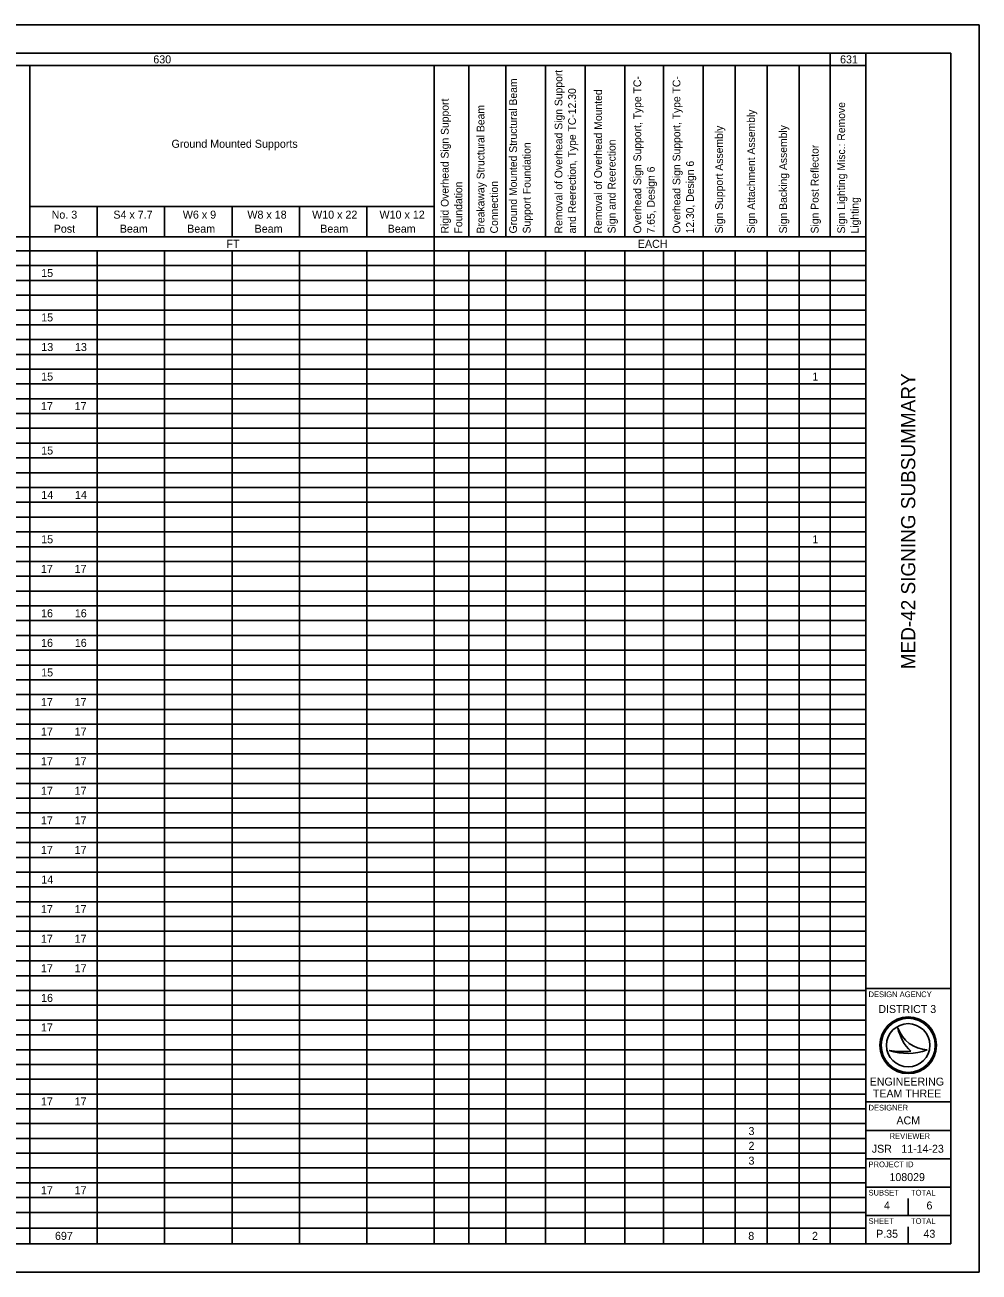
# Model space of a CAD drawing. Extents: x 0 to 34, y 0 to 22.
# Drawn here: x 17.17 to 34, y 0 to 22 of the extents above; entities that cross this region are included whole.
import ezdxf

# ---------------------------------------------------------------- set-up
doc = ezdxf.new("R2010")
doc.units = 0
for name, color, linetype in [('SH_Border', 7, 'Continuous'), ('SH_Cut_Line', 7, 'Continuous'), ('SH_Data', 7, 'Continuous'), ('SH_Text', 7, 'Continuous')]:
    doc.layers.add(name, color=color, linetype=linetype)

msp = doc.modelspace()

# ---------------------------------------------------------------- linework, layer by layer
at = {"layer": 'SH_Border'}
for p, q in [((32, 0.5), (32, 21.5)), ((32, 5), (33.5, 5)), ((32, 3), (33.5, 3)), ((32, 2.5), (33.5, 2.5)), ((32, 2), (33.5, 2)), ((32, 1.5), (33.5, 1.5)), ((32, 1), (33.5, 1))]:
    msp.add_line(p, q, dxfattribs=at)
msp.add_lwpolyline([(1.5, 21.5), (33.5, 21.5), (33.5, 0.5), (1.5, 0.5)], close=True, dxfattribs=at)
at = {"layer": 'SH_Cut_Line'}
msp.add_lwpolyline([(0, 0), (34, 0), (34, 22), (0, 22)], close=True, dxfattribs=at)
at = {"layer": 'SH_Data'}
for p, q in [((32.567, 4.31), (32.567, 4.31)), ((32.75, 4), (32.75, 4)), ((32.417, 3.91), (32.417, 3.91)), ((33.087, 3.919), (33.087, 3.919)), ((32.75, 1), (32.75, 1.3)), ((32.375, 0.675), (32.375, 0.675)), ((32.75, 0.5), (32.75, 0.8))]:
    msp.add_line(p, q, dxfattribs=at)
for radius in [0.5, 0.477, 0.477, 0.382]:
    msp.add_circle((32.75, 4), radius, dxfattribs=at)
for centre, radius, start, end in [((33.116, 4.498), 0.58, 198.9257, 198.9319), ((33.347, 4.47), 0.796, 191.6379, 191.6421), ((33.116, 4.498), 0.58, 198.9319, 267.1657), ((33.347, 4.47), 0.796, 191.6421, 226.0947), ((32.739, 4.87), 1.013, 251.4576, 290.0832), ((32.648, 5.154), 1.266, 259.4964, 259.4995), ((32.739, 4.87), 1.013, 251.4527, 251.4576), ((32.648, 5.154), 1.266, 259.4995, 276.6672)]:
    msp.add_arc(centre, radius, start, end, dxfattribs=at)
at = {"layer": 'SH_Text'}
for p, q in [((1.5, 21.5), (32, 21.5)), ((31.376, 21.5), (31.376, 18.261)), ((32, 21.5), (32, 18.015)), ((7.787, 21.285), (32, 21.285)), ((17.255, 21.285), (17.255, 18.015)), ((24.39, 21.285), (24.39, 18.015)), ((24.999, 21.285), (24.999, 18.261)), ((25.653, 21.285), (25.653, 18.261)), ((26.352, 21.285), (26.352, 18.261)), ((27.05, 21.285), (27.05, 18.261)), ((27.749, 21.285), (27.749, 18.261)), ((28.433, 21.285), (28.433, 18.261)), ((29.131, 21.285), (29.131, 18.261)), ((29.696, 21.285), (29.696, 18.261)), ((30.261, 21.285), (30.261, 18.261)), ((30.826, 21.285), (30.826, 18.261)), ((17.255, 18.798), (24.39, 18.798)), ((18.444, 18.798), (18.444, 18.261)), ((19.634, 18.798), (19.634, 18.261)), ((20.823, 18.798), (20.823, 18.261)), ((22.012, 18.798), (22.012, 18.261)), ((23.201, 18.798), (23.201, 18.261)), ((6.658, 18.261), (32, 18.261)), ((1.5, 18.015), (32, 18.015)), ((17.255, 18.015), (17.255, 0.5)), ((18.444, 18.015), (18.444, 0.5)), ((19.634, 18.015), (19.634, 0.5)), ((20.823, 18.015), (20.823, 0.5)), ((22.012, 18.015), (22.012, 0.5)), ((23.201, 18.015), (23.201, 0.5)), ((24.39, 18.015), (24.39, 0.5)), ((24.999, 18.015), (24.999, 0.5)), ((25.653, 18.015), (25.653, 0.5)), ((26.352, 18.015), (26.352, 0.5)), ((27.05, 18.015), (27.05, 0.5)), ((27.749, 18.015), (27.749, 0.5)), ((28.433, 18.015), (28.433, 0.5)), ((29.131, 18.015), (29.131, 0.5)), ((29.696, 18.015), (29.696, 0.5)), ((30.261, 18.015), (30.261, 0.5)), ((30.826, 18.015), (30.826, 0.5)), ((31.376, 18.015), (31.376, 0.5)), ((32, 18.015), (32, 0.5)), ((1.5, 17.754), (32, 17.754)), ((1.5, 17.493), (32, 17.493)), ((1.5, 17.232), (32, 17.232)), ((1.5, 16.971), (32, 16.971)), ((1.5, 16.711), (32, 16.711)), ((1.5, 16.45), (32, 16.45)), ((1.5, 16.189), (32, 16.189)), ((1.5, 15.928), (32, 15.928)), ((1.5, 15.667), (32, 15.667)), ((1.5, 15.406), (32, 15.406)), ((1.5, 15.145), (32, 15.145)), ((1.5, 14.884), (32, 14.884)), ((1.5, 14.623), (32, 14.623)), ((1.5, 14.362), (32, 14.362)), ((1.5, 14.101), (32, 14.101)), ((1.5, 13.84), (32, 13.84)), ((1.5, 13.579), (32, 13.579)), ((1.5, 13.318), (32, 13.318)), ((1.5, 13.057), (32, 13.057)), ((1.5, 12.796), (32, 12.796)), ((1.5, 12.535), (32, 12.535)), ((1.5, 12.274), (32, 12.274)), ((1.5, 12.013), (32, 12.013)), ((1.5, 11.752), (32, 11.752)), ((1.5, 11.491), (32, 11.491)), ((1.5, 11.23), (32, 11.23)), ((1.5, 10.969), (32, 10.969)), ((1.5, 10.708), (32, 10.708)), ((1.5, 10.447), (32, 10.447)), ((1.5, 10.186), (32, 10.186)), ((1.5, 9.925), (32, 9.925)), ((1.5, 9.664), (32, 9.664)), ((1.5, 9.404), (32, 9.404)), ((1.5, 9.143), (32, 9.143)), ((1.5, 8.882), (32, 8.882)), ((1.5, 8.621), (32, 8.621)), ((1.5, 8.36), (32, 8.36)), ((1.5, 8.099), (32, 8.099)), ((1.5, 7.838), (32, 7.838)), ((1.5, 7.577), (32, 7.577)), ((1.5, 7.316), (32, 7.316)), ((1.5, 7.055), (32, 7.055)), ((1.5, 6.794), (32, 6.794)), ((1.5, 6.533), (32, 6.533)), ((1.5, 6.272), (32, 6.272)), ((1.5, 6.011), (32, 6.011)), ((1.5, 5.75), (32, 5.75)), ((1.5, 5.489), (32, 5.489)), ((1.5, 5.228), (32, 5.228)), ((1.5, 4.967), (32, 4.967)), ((1.5, 4.706), (32, 4.706)), ((1.5, 4.445), (32, 4.445)), ((1.5, 4.184), (32, 4.184)), ((1.5, 3.923), (32, 3.923)), ((1.5, 3.662), (32, 3.662)), ((1.5, 3.401), (32, 3.401)), ((1.5, 3.14), (32, 3.14)), ((1.5, 2.879), (32, 2.879)), ((1.5, 2.618), (32, 2.618)), ((1.5, 2.357), (32, 2.357)), ((1.5, 2.096), (32, 2.096)), ((1.5, 1.836), (32, 1.836)), ((1.5, 1.575), (32, 1.575)), ((1.5, 1.314), (32, 1.314)), ((1.5, 1.053), (32, 1.053)), ((1.5, 0.776), (32, 0.776)), ((1.5, 0.5), (32, 0.5))]:
    msp.add_line(p, q, dxfattribs=at)

# ---------------------------------------------------------------- texts
at = {"layer": 'SH_Data'}
msp.add_text('MED-42 SIGNING SUBSUMMARY', height=0.25, rotation=90, dxfattribs=at).set_placement((32.875, 10.634))
for s, height, p in [('DESIGN AGENCY', 0.1, (32.05, 4.85)), ('DISTRICT 3', 0.14, (32.224, 4.57)), ('ENGINEERING', 0.14, (32.071, 3.29)), ('TEAM THREE', 0.14, (32.127, 3.08)), ('DESIGNER', 0.1, (32.05, 2.85)), ('ACM', 0.14, (32.543, 2.605)), ('REVIEWER', 0.1, (32.422, 2.35)), ('JSR', 0.14, (32.108, 2.105)), ('11-14-23', 0.14, (32.629, 2.105)), ('PROJECT ID', 0.1, (32.05, 1.85)), ('SUBSET', 0.1, (32.05, 1.35)), ('TOTAL', 0.1, (32.8, 1.35)), ('4', 0.14, (32.322, 1.105)), ('6', 0.14, (33.073, 1.105)), ('SHEET', 0.1, (32.05, 0.85)), ('TOTAL', 0.1, (32.8, 0.85)), ('P.35', 0.14, (32.185, 0.605)), ('43', 0.14, (33.02, 0.605))]:
    msp.add_text(s, height=height, dxfattribs=at).set_placement(p)
at = {"layer": 'SH_Text'}
for s, height, p in [('630', 0.1412, (19.434, 21.322)), ('631', 0.1412, (31.548, 21.322)), ('Ground Mounted Supports', 0.14123, (19.755, 19.833)), ('No. 3', 0.1412, (17.64, 18.583)), ('S4 x 7.7', 0.1412, (18.729, 18.583)), ('W6 x 9', 0.1412, (19.954, 18.583)), ('W8 x 18', 0.1412, (21.093, 18.583)), ('W10 x 22 ', 0.1412, (22.235, 18.583)), ('W10 x 12 ', 0.1412, (23.424, 18.583)), ('Post', 0.1412, (17.677, 18.335)), (' Beam', 0.1412, (18.79, 18.335)), (' Beam', 0.1412, (19.979, 18.335)), (' Beam', 0.1412, (21.168, 18.335)), ('Beam', 0.1412, (22.379, 18.335)), ('Beam', 0.1412, (23.568, 18.335)), ('FT', 0.1412, (20.723, 18.068)), ('EACH', 0.1412, (27.98, 18.068)), ('15', 0.1412, (17.456, 17.553)), ('15', 0.1412, (17.456, 16.77)), ('13', 0.1412, (17.458, 16.248)), ('13', 0.1412, (18.052, 16.248)), ('15', 0.1412, (17.456, 15.727)), ('1', 0.141, (31.06, 15.727)), ('17', 0.1412, (17.452, 15.205)), ('17', 0.1412, (18.046, 15.205)), ('15', 0.1412, (17.456, 14.422)), ('14', 0.1412, (17.458, 13.639)), ('14', 0.1412, (18.052, 13.639)), ('15', 0.1412, (17.456, 12.856)), ('1', 0.141, (31.06, 12.856)), ('17', 0.1412, (17.452, 12.334)), ('17', 0.1412, (18.046, 12.334)), ('16', 0.1412, (17.454, 11.551)), ('16', 0.1412, (18.049, 11.551)), ('16', 0.1412, (17.454, 11.029)), ('16', 0.1412, (18.049, 11.029)), ('15', 0.1412, (17.456, 10.507)), ('17', 0.1412, (17.452, 9.985)), ('17', 0.1412, (18.046, 9.985)), ('17', 0.1412, (17.452, 9.463)), ('17', 0.1412, (18.046, 9.463)), ('17', 0.1412, (17.452, 8.941)), ('17', 0.1412, (18.046, 8.941)), ('17', 0.1412, (17.452, 8.42)), ('17', 0.1412, (18.046, 8.42)), ('17', 0.1412, (17.452, 7.898)), ('17', 0.1412, (18.046, 7.898)), ('17', 0.1412, (17.452, 7.376)), ('17', 0.1412, (18.046, 7.376)), ('14', 0.1412, (17.458, 6.854)), ('17', 0.1412, (17.452, 6.332)), ('17', 0.1412, (18.046, 6.332)), ('17', 0.1412, (17.452, 5.81)), ('17', 0.1412, (18.046, 5.81)), ('17', 0.1412, (17.452, 5.288)), ('17', 0.1412, (18.046, 5.288)), ('16', 0.1412, (17.454, 4.766)), ('17', 0.1412, (17.452, 4.244)), ('17', 0.1412, (17.452, 2.939)), ('17', 0.1412, (18.046, 2.939)), ('3', 0.141, (29.933, 2.417)), ('2', 0.141, (29.933, 2.156)), ('3', 0.141, (29.933, 1.895)), ('108029', 0.14, (32.42, 1.605)), ('17', 0.1412, (17.452, 1.373)), ('17', 0.1412, (18.046, 1.373)), ('697', 0.1412, (17.699, 0.568)), ('8', 0.141, (29.929, 0.568)), ('2', 0.141, (31.053, 0.568))]:
    msp.add_text(s, height=height, dxfattribs=at).set_placement(p)
for s, height, p in [('Removal of Overhead Sign Support ', 0.13674, (26.65, 18.322)), ('Ground Mounted Structural Beam ', 0.13674, (25.849, 18.322)), ('Overhead Sign Support, Type TC-', 0.13674, (28.04, 18.322)), ('Overhead Sign Support, Type TC-', 0.13674, (28.731, 18.322)), ('Rigid Overhead Sign Support ', 0.13674, (24.643, 18.322)), ('and Reerection, Type TC-12.30', 0.13674, (26.889, 18.322)), ('Removal of Overhead Mounted    ', 0.13674, (27.348, 18.322)), ('Breakaway Structural Beam ', 0.13674, (25.275, 18.322)), ('Sign Attachment Assembly', 0.13674, (30.047, 18.322)), ('Sign Lighting Misc.: Remove ', 0.13674, (31.637, 18.322)), ('Sign Support Assembly', 0.13674, (29.482, 18.322)), ('Sign Backing Assembly', 0.13674, (30.612, 18.322)), ('Support Foundation', 0.13674, (26.089, 18.322)), ('Sign and Reerection', 0.13674, (27.588, 18.322)), ('Sign Post Reflector', 0.13674, (31.169, 18.322)), ('12.30, Design 6', 0.13674, (28.97, 18.322)), ('7.65, Design 6', 0.13674, (28.279, 18.322)), ('Foundation', 0.1367, (24.883, 18.322)), ('Connection', 0.1367, (25.514, 18.322)), ('Lighting', 0.1367, (31.876, 18.322))]:
    msp.add_text(s, height=height, rotation=90, dxfattribs=at).set_placement(p)

doc.saveas('drawing.dxf')
